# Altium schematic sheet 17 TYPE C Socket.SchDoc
size 420 x 297 mm
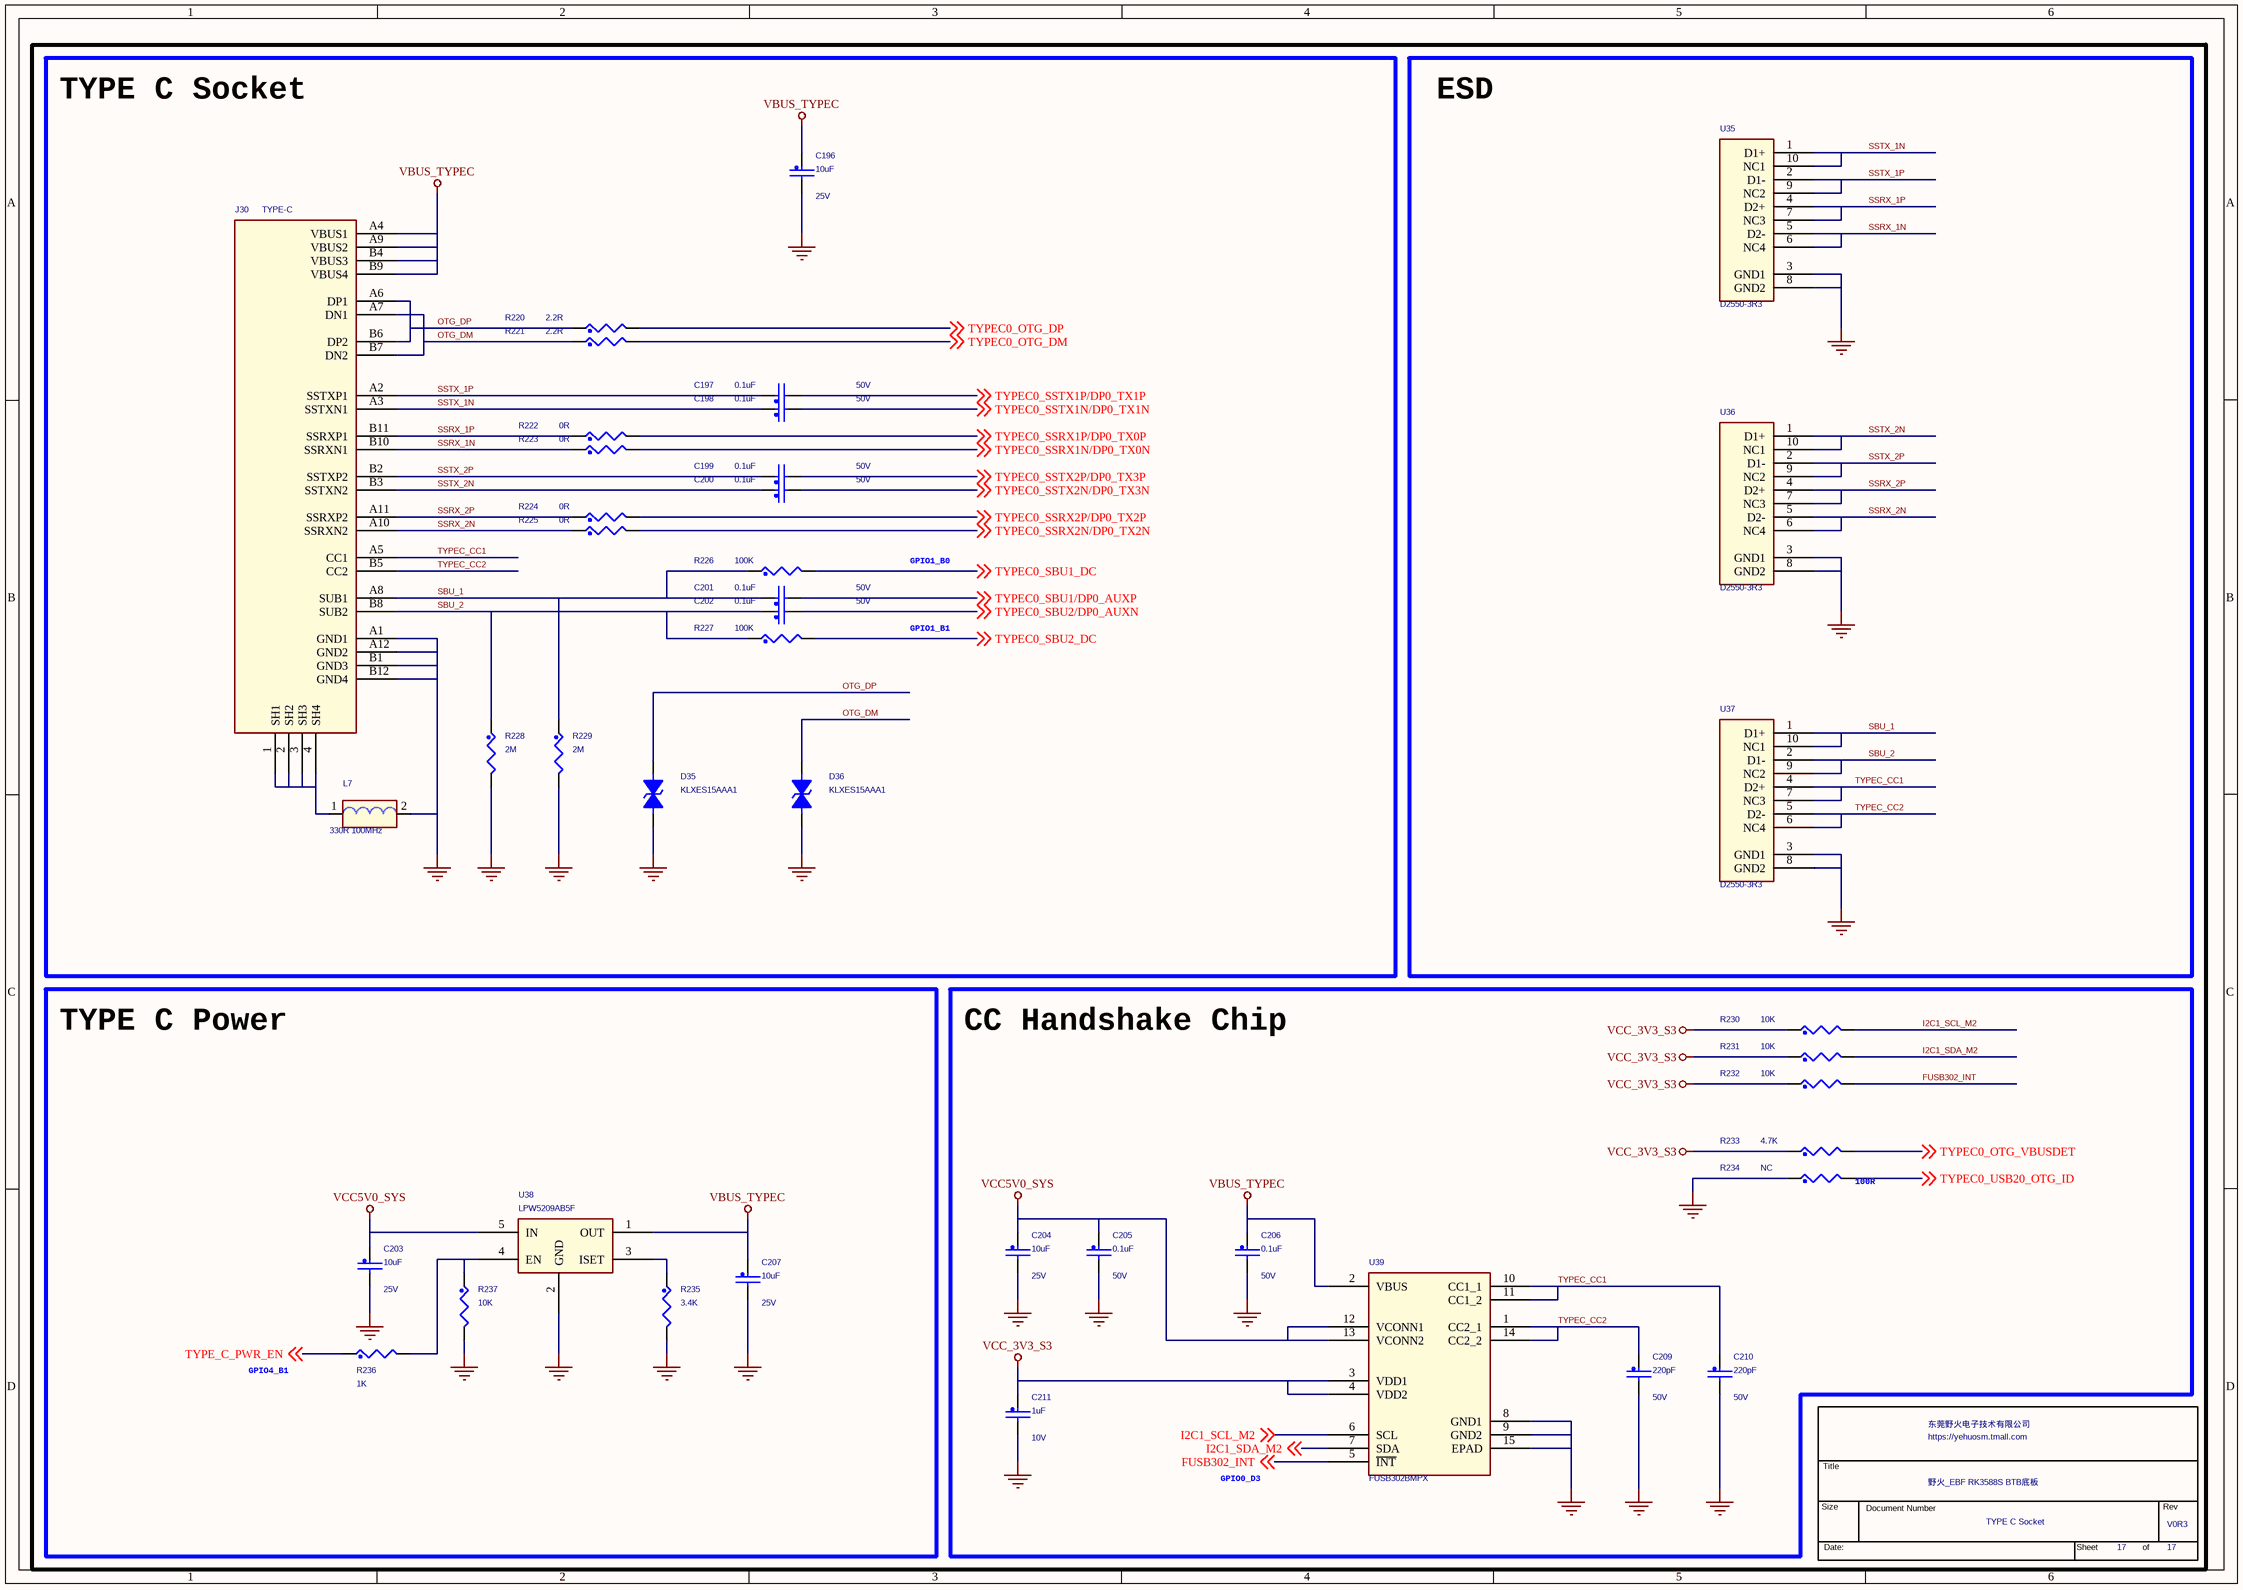
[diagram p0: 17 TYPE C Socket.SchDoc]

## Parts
*  Page Count: 17  OrgName: 东莞野火电子技术有限公司  Title: 野火_EBF RK3588S BTB底板  RevCode: V0R3  Doc: TYPE C Socket  (hidden comment: TitleBlock_YHSCH)  (graphical)
C196  10uF  Voltage: 25V  [C0603]
C197  0.1uF  Voltage: 50V  [C0402]
C198  0.1uF  Voltage: 50V  [C0402]
C199  0.1uF  Voltage: 50V  [C0402]
C200  0.1uF  Voltage: 50V  [C0402]
C201  0.1uF  Voltage: 50V  [C0402]
C202  0.1uF  Voltage: 50V  [C0402]
C203  10uF  Voltage: 25V  [C0603]
C204  10uF  Voltage: 25V  [C0603]
C205  0.1uF  Voltage: 50V  [C0402]
C206  0.1uF  Voltage: 50V  [C0402]
C207  10uF  Voltage: 25V  [C0603]
C209  220pF  Voltage: 50V  [C0402]
C210  220pF  Voltage: 50V  [C0402]
C211  1uF  Voltage: 10V  [C0402]
D35  KLXES15AAA1  [D0603/SMD]
D36  KLXES15AAA1  [D0603/SMD]
J30  TYPE-C  [usb-c-smd_tyc-324g]
L7  330R 100MHz  [L0603]
R220  2.2R  [R0402]
R221  2.2R  [R0402]
R222  0R  [R0402]
R223  0R  [R0402]
R224  0R  [R0402]
R225  0R  [R0402]
R226  100K  [R0402]
R227  100K  [R0402]
R228  2M  [R0402]
R229  2M  [R0402]
R230  10K  [R0402]
R231  10K  [R0402]
R232  10K  [R0402]
R233  4.7K  [R0402]
R234  NC  [R0402]
R235  3.4K  [R0402]
R236  1K  [R0402]
R237  10K  [R0402]
U35  D2550-3R3  [son10_2r50x1r00x0r50]
U36  D2550-3R3  [son10_2r50x1r00x0r50]
U37  D2550-3R3  [son10_2r50x1r00x0r50]
U38  LPW5209AB5F  [SOT23-5]
U39  FUSB302BMPX  [WQFN14-0R50-2R5X2R5EP1R45X1R45]

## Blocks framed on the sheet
TYPE C Socket: C196-C202 D35 D36 J30 L7 R220-R229
ESD: U35-U37
TYPE C Power: C203 C207 R235-R237 U38
CC Handshake Chip: C204-C206 C209-C211 R230-R234 U39

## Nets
GND: C196.2 C203.2 C204.2 C205.2 C206.2 C207.2 C209.2 C210.2 C211.2 D35.2 D36.2 J30.A1(GND1) J30.A12(GND2) J30.B1(GND3) J30.B12(GND4) L7.2 R228.2 R229.2 R234.1 R235.2 R237.2 U35.3(GND1) U35.8(GND2) U36.3(GND1) U36.8(GND2) U37.3(GND1) U37.8(GND2) U38.2(GND) U39.8(GND1) U39.9(GND2) U39.15(EPAD)
VBUS_TYPEC: C196.1 C206.1 C207.1 J30.A4(VBUS1) J30.A9(VBUS2) J30.B4(VBUS3) J30.B9(VBUS4) U38.1(OUT) U39.2(VBUS)
VCC5V0_SYS: C203.1 C204.1 C205.1 U38.5(IN) U39.12(VCONN1) U39.13(VCONN2)
VCC_3V3_S3: C211.1 R230.1 R231.1 R232.1 R233.1 U39.3(VDD1) U39.4(VDD2)
FUSB302_INT: R232.2 U39.5(~{INT}) ; off-sheet FUSB302_INT
I2C1_SCL_M2: R230.2 U39.6(SCL) ; off-sheet I2C1_SCL_M2
I2C1_SDA_M2: R231.2 U39.7(SDA) ; off-sheet I2C1_SDA_M2
OTG_DM: D36.1 J30.A7(DN1) J30.B7(DN2) R221.1
OTG_DP: D35.1 J30.A6(DP1) J30.B6(DP2) R220.1
SBU_1: C201.1 J30.A8(SUB1) R226.1 R229.1 U37.1(D1+) U37.10(NC1)
SBU_2: C202.1 J30.B8(SUB2) R227.1 R228.1 U37.2(D1-) U37.9(NC2)
SSRX_1N: J30.B10(SSRXN1) R223.1 U35.5(D2-) U35.6(NC4)
SSRX_1P: J30.B11(SSRXP1) R222.1 U35.4(D2+) U35.7(NC3)
SSRX_2N: J30.A10(SSRXN2) R225.1 U36.5(D2-) U36.6(NC4)
SSRX_2P: J30.A11(SSRXP2) R224.1 U36.4(D2+) U36.7(NC3)
SSTX_1N: C198.1 J30.A3(SSTXN1) U35.1(D1+) U35.10(NC1)
SSTX_1P: C197.1 J30.A2(SSTXP1) U35.2(D1-) U35.9(NC2)
SSTX_2N: C200.1 J30.B3(SSTXN2) U36.1(D1+) U36.10(NC1)
SSTX_2P: C199.1 J30.B2(SSTXP2) U36.2(D1-) U36.9(NC2)
TYPE_C_PWR_EN: R236.1 ; off-sheet TYPE_C_PWR_EN
TYPEC0_OTG_DM: R221.2 ; off-sheet TYPEC0_OTG_DM
TYPEC0_OTG_DP: R220.2 ; off-sheet TYPEC0_OTG_DP
TYPEC0_OTG_VBUSDET: R233.2 ; off-sheet TYPEC0_OTG_VBUSDET
TYPEC0_SBU1/DP0_AUXP: C201.2 ; off-sheet TYPEC0_SBU1/DP0_AUXP
TYPEC0_SBU1_DC: R226.2 ; off-sheet TYPEC0_SBU1_DC
TYPEC0_SBU2/DP0_AUXN: C202.2 ; off-sheet TYPEC0_SBU2/DP0_AUXN
TYPEC0_SBU2_DC: R227.2 ; off-sheet TYPEC0_SBU2_DC
TYPEC0_SSRX1N/DP0_TX0N: R223.2 ; off-sheet TYPEC0_SSRX1N/DP0_TX0N
TYPEC0_SSRX1P/DP0_TX0P: R222.2 ; off-sheet TYPEC0_SSRX1P/DP0_TX0P
TYPEC0_SSRX2N/DP0_TX2N: R225.2 ; off-sheet TYPEC0_SSRX2N/DP0_TX2N
TYPEC0_SSRX2P/DP0_TX2P: R224.2 ; off-sheet TYPEC0_SSRX2P/DP0_TX2P
TYPEC0_SSTX1N/DP0_TX1N: C198.2 ; off-sheet TYPEC0_SSTX1N/DP0_TX1N
TYPEC0_SSTX1P/DP0_TX1P: C197.2 ; off-sheet TYPEC0_SSTX1P/DP0_TX1P
TYPEC0_SSTX2N/DP0_TX3N: C200.2 ; off-sheet TYPEC0_SSTX2N/DP0_TX3N
TYPEC0_SSTX2P/DP0_TX3P: C199.2 ; off-sheet TYPEC0_SSTX2P/DP0_TX3P
TYPEC0_USB20_OTG_ID: R234.2 ; off-sheet TYPEC0_USB20_OTG_ID
TYPEC_CC1: C210.1 J30.A5(CC1) U37.4(D2+) U37.7(NC3) U39.10(CC1_1) U39.11(CC1_2)
TYPEC_CC2: C209.1 J30.B5(CC2) U37.5(D2-) U37.6(NC4) U39.1(CC2_1) U39.14(CC2_2)
NetJ30_1: J30.1(SH1) J30.2(SH2) J30.3(SH3) J30.4(SH4) L7.1
NetR235_1: R235.1 U38.3(ISET)
NetR236_2: R236.2 R237.1 U38.4(EN)

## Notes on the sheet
- GPIO1_B0
- GPIO1_B1
- (near R234) 100R
- GPIO4_B1
- GPIO0_D3

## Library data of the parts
* = TitleBlock_YHSCH: Cage Code: 1
C196 C204 C207 = CAP_NP: CLASS: DISCRETE; 规格: 贴片电容10uF 20% 25V X5R 0603; 规格编号: CL10A106MA8NRNC; 条码: EBF29060171; 品牌: 三星; 类别: 贴片电容0603; 规格书: 三星电容.pdf; 价格: 0.109811; 生命周期: 量产
C197 C199 C200 C202 C205 C206 = CAP_NP: CLASS: DISCRETE; 生命周期: 量产; 价格: 0.029826; 规格书: 风华电容.pdf; 类别: 贴片电容0402; 品牌: 风华; 条码: EBF29060118; 规格编号: 0402X104K500NT; 规格: 贴片电容0.1uF 10% 50V X5R 0402
C198 C201 = CAP_NP: CLASS: DISCRETE; 规格: 贴片电容0.1uF 10% 50V X5R 0402; 规格编号: 0402X104K500NT; 条码: EBF29060118; 品牌: 风华; 类别: 贴片电容0402; 规格书: 风华电容.pdf; 价格: 0.029826; 生命周期: 量产
C203 = CAP_NP: CLASS: DISCRETE; 生命周期: 量产; 价格: 0.109811; 规格书: 三星电容.pdf; 类别: 贴片电容0603; 品牌: 三星; 条码: EBF29060171; 规格编号: CL10A106MA8NRNC; 规格: 贴片电容10uF 20% 25V X5R 0603
C209 = CAP_NP: CLASS: DISCRETE; 价格: 0.00358; 规格书: 风华电容.pdf; 类别: 贴片电容0402; 品牌: 风华; 条码: EBFCIS221112143723; 规格编号: 0402B221K500NT; 规格: 贴片电容220pF 10% 50V X7R 0402
C210 = CAP_NP: CLASS: DISCRETE; 规格: 贴片电容220pF 10% 50V X7R 0402; 规格编号: 0402B221K500NT; 条码: EBFCIS221112143723; 品牌: 风华; 类别: 贴片电容0402; 规格书: 风华电容.pdf; 价格: 0.00358
C211 = CAP_NP: CLASS: DISCRETE; 生命周期: 量产; 价格: 0.01191; 规格书: 风华电容.pdf; 类别: 贴片电容0402; 品牌: 风华; 条码: EBF29060121; 规格编号: 0402X105K100NT; 规格: 贴片电容1uF 10% 10V X5R 0402
D35 = DIODE BI-DIR TRIG: 生命周期: 量产; 价格: 0.09719; 规格书: KLXES15AAA1.pdf; 类别: 贴片ESD; 品牌: 永裕泰; 条码: EBF29140063; 规格: 用于 USB3.0、HDMI 0.5pF、5V、±15kV ESD 保护二极管
D36 = DIODE BI-DIR TRIG: 规格: 用于 USB3.0、HDMI 0.5pF、5V、±15kV ESD 保护二极管; 条码: EBF29140063; 品牌: 永裕泰; 类别: 贴片ESD; 规格书: KLXES15AAA1.pdf; 价格: 0.09719; 生命周期: 量产
J30 = TYPE-C-24P: 规格书: 讯普_TYC-324G.pdf; 类别: USB接口; 品牌: 讯普; 条码: EBFCIS220922094113; 规格编号: TYC-324G; 规格: Type-C母座 24P USB-3.1 插座 4固定脚 双向
L7 = BEAD: CLASS: DISCRETE; 生命周期: 量产; 规格书: TDK-MPZ1608S331ATA00.pdf; 类别: 贴片磁珠0603; 品牌: TDK; 条码: EBF29050003; 规格编号: MPZ1608S331ATA00; 规格: 磁珠330Ω @100MHz 额定电流1.7A 直流电阻80mΩ
R220 = RES: CLASS: DISCRETE; 规格: 贴片电阻2.2R 1% 1/16W 0402; 规格编号: 0402WGF220KTCE; 条码: EBF29070280; 品牌: 厚声; 类别: 贴片电阻0402; 规格书: 厚声-无铅厚膜电阻.pdf; 价格: 0.003072; 生命周期: 量产
R221 = RES: CLASS: DISCRETE; 生命周期: 量产; 价格: 0.003072; 规格书: 厚声-无铅厚膜电阻.pdf; 类别: 贴片电阻0402; 品牌: 厚声; 条码: EBF29070280; 规格编号: 0402WGF220KTCE; 规格: 贴片电阻2.2R 1% 1/16W 0402
R222-R225 = RES: CLASS: DISCRETE; 生命周期: 量产; 规格书: 合科泰-RI系列电阻.pdf; 类别: 贴片电阻0402; 品牌: 合科泰; 条码: EBF29070049; 规格编号: RI0402L000FT; 规格: 贴片电阻0R 1% 1/16W 0402
R226 = RES: CLASS: DISCRETE; 生命周期: 量产; 规格书: 合科泰-RI系列电阻.pdf; 类别: 贴片电阻0402; 品牌: 合科泰; 条码: EBF29070054; 规格编号: RI0402L1003FT; 规格: 贴片电阻100K 1% 1/16W 0402
R227 = RES: CLASS: DISCRETE; 规格: 贴片电阻100K 1% 1/16W 0402; 规格编号: RI0402L1003FT; 条码: EBF29070054; 品牌: 合科泰; 类别: 贴片电阻0402; 规格书: 合科泰-RI系列电阻.pdf; 生命周期: 量产
R228 R229 = RES: CLASS: DISCRETE; 生命周期: 量产; 规格: 贴片电阻2M 1% 1/16W 0402; 规格编号: 0402WGF2004TCE; 条码: EBFCIS221112151157; 品牌: 厚声; 类别: 贴片电阻0402; 规格书: 厚声-无铅厚膜电阻.pdf; 价格: 0.002023
R230-R232 = RES: CLASS: DISCRETE; 生命周期: 量产; 规格书: 厚声-无铅厚膜电阻.pdf; 类别: 贴片电阻0402; 品牌: 厚声; 条码: EBF29070046; 规格编号: 0402WGF1002TCE; 规格: 贴片电阻10K 1% 1/16W 0402; 价格: 0.002773
R233 = RES: CLASS: DISCRETE; 规格: 贴片电阻4.7K 1% 1/16W 0402; 规格编号: RI0402L4701FT; 条码: EBF29070047; 品牌: 合科泰; 类别: 贴片电阻0402; 规格书: 合科泰-RI系列电阻.pdf; 生命周期: 量产
R234 = RES: CLASS: DISCRETE; 规格: 贴片电阻NC 预留; 条码: EBF29070087; 类别: 贴片电阻0402
R235 = RES: CLASS: DISCRETE; 规格: 贴片电阻3.4K 1% 1/16W 0402; 规格编号: RI0402L3401FT; 条码: EBF29070186; 品牌: 合科泰; 类别: 贴片电阻0402; 规格书: 合科泰-RI系列电阻.pdf; 生命周期: 量产
R236 = RES: CLASS: DISCRETE; 生命周期: 量产; 规格书: 合科泰-RI系列电阻.pdf; 类别: 贴片电阻0402; 品牌: 合科泰; 条码: EBF29070050; 规格编号: RI0402L1001FT; 规格: 贴片电阻1K 1% 1/16W 0402
R237 = RES: CLASS: DISCRETE; 生命周期: 量产; 价格: 0.002773; 规格书: 厚声-无铅厚膜电阻.pdf; 类别: 贴片电阻0402; 品牌: 厚声; 条码: EBF29070046; 规格编号: 0402WGF1002TCE; 规格: 贴片电阻10K 1% 1/16W 0402
U35-U37 = RCLAMP0524P: 丝印: 3324P; 备注: 猫5 HDMI2.1新物料; 生命周期: 量产; 规格书: 千虹_D2550-3R3.pdf; 类别: 贴片四路ESD; 品牌: 千虹; 条码: EBFCIS231110170954; 规格: 用于 USB3.0、HDMI2.1和高速接口的四路0.13pF、3.3V、±12kV ESD 保护二极管
U38 = LPW5209AB5F: 生命周期: 量产; 价格: 0.468063; 规格书: 微源半导体_LPW5209AB5F.pdf; 类别: 功率开关; 品牌: 微源半导体; 条码: EBF29280015; 规格: 集成电源开关 导通电阻：80mΩ 最大可设置保护电流：2.1A 输入电压：2.5V~6V 静态电流：30uA 其他功能：软启动、短路保护、热保护
U39 = FUSB302BMPX: 生命周期: 量产; 价格: 3.8016; 规格书: 安森美_FUSB302BMPX.pdf; 类别: USB芯片; 品牌: 安森美; 条码: EBFCIS221116112239; 规格: 可编程USB Type-C控制器 支持USB Type-C检测 带PD 可实现高达 100 W 的电源和角色互换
